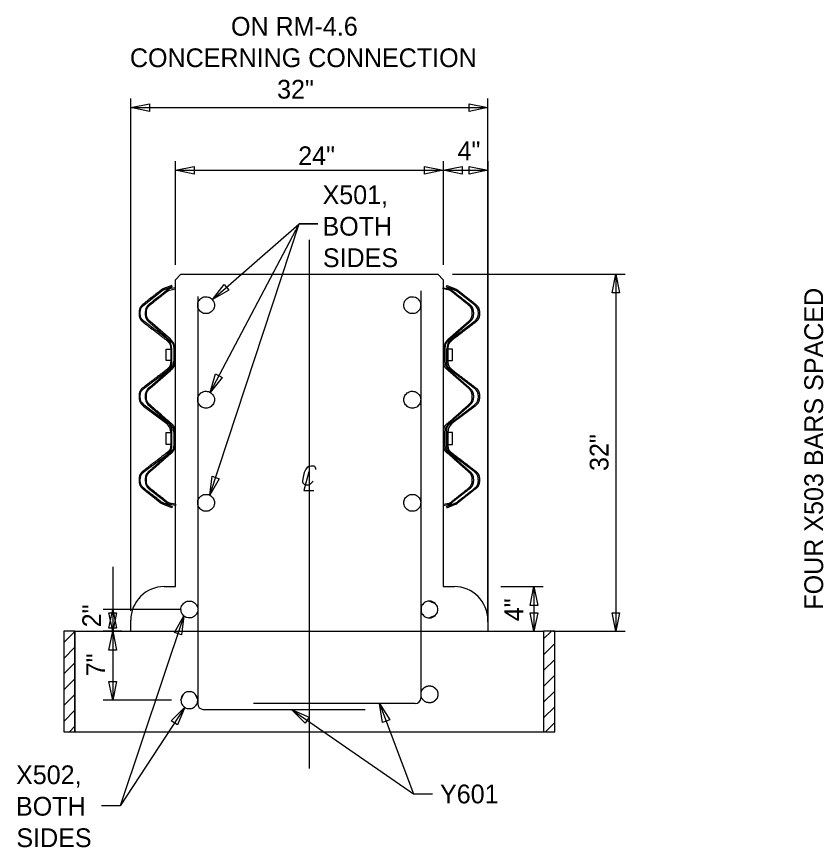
# Model space of a CAD drawing. Extents: x 0 to 680, y 0 to 440.
# Drawn here: x 167 to 287.1, y 191.7 to 315.4 of the extents above; entities that cross this region are included whole.
import ezdxf

# ---------------------------------------------------------------- set-up
doc = ezdxf.new("R2010")
doc.units = 0
doc.layers.add('Default', color=7, linetype='Continuous')

msp = doc.modelspace()

# ---------------------------------------------------------------- linework, layer by layer
at = {"layer": 'Default'}
for p, q in [((183.96, 226.91), (183.96, 303.25)), ((183.96, 301.87), (237.16, 301.87)), ((190.61, 278.45), (190.61, 293.91)), ((230.51, 293.91), (230.51, 278.45)), ((195.76, 244.12), (209.03, 284.55)), ((195.79, 259.44), (209.03, 284.55)), ((196.12, 273.27), (209.03, 284.55)), ((209.03, 284.55), (211.83, 284.55)), ((211.83, 284.55), (209.03, 284.55)), ((210.56, 282.16), (210.56, 203.44)), ((231.89, 277.04), (257.61, 277.04)), ((256.22, 277.04), (256.22, 223.86)), ((190.08, 275.38), (188.75, 274.85)), ((190.61, 275.04), (189.69, 274.85)), ((189.72, 274.68), (190.61, 274.85)), ((190.13, 275.18), (190.08, 275.38)), ((190.61, 274.85), (190.61, 275.04)), ((230.51, 275.04), (231.42, 274.85)), ((230.51, 274.85), (230.51, 275.04)), ((231.39, 274.68), (230.51, 274.85)), ((230.98, 275.18), (231.03, 275.38)), ((231.03, 275.38), (232.36, 274.85)), ((185.95, 272.49), (188.61, 274.57)), ((187.09, 273.38), (187, 273.55)), ((188, 273.38), (187.89, 273.55)), ((188.19, 274.24), (188.08, 274.41)), ((189.08, 274.24), (189, 274.38)), ((193.93, 273.71), (193.93, 213.06)), ((227.18, 274.57), (227.18, 213.92)), ((232.03, 274.24), (232.11, 274.38)), ((235.16, 272.49), (232.5, 274.57)), ((232.95, 274.24), (233.03, 274.41)), ((233.11, 273.38), (233.22, 273.55)), ((234.03, 273.38), (234.11, 273.55)), ((189.41, 267.37), (185.98, 270)), ((189.86, 267.37), (186.86, 270)), ((231.26, 267.37), (234.25, 270)), ((231.7, 267.37), (235.14, 270)), ((187.09, 269.14), (186.98, 268.97)), ((187.95, 269.06), (187.83, 268.89)), ((233.17, 269.06), (233.28, 268.89)), ((234.03, 269.14), (234.14, 268.97)), ((188.19, 268.31), (188.08, 268.14)), ((189, 268.12), (188.92, 267.98)), ((232.11, 268.12), (232.2, 267.98)), ((232.92, 268.31), (233.03, 268.14)), ((190.08, 265.65), (189.91, 265.65)), ((190.08, 264.13), (190.08, 265.95)), ((190.36, 265.95), (190.36, 264.13)), ((190.52, 265.65), (190.36, 265.65)), ((190.52, 264.13), (190.52, 265.95)), ((230.59, 264.13), (230.59, 265.95)), ((230.59, 265.65), (230.76, 265.65)), ((230.76, 265.95), (230.76, 264.13)), ((231.03, 264.13), (231.03, 265.95)), ((231.03, 265.65), (231.2, 265.65)), ((190.08, 264.43), (189.91, 264.43)), ((190.52, 264.43), (190.36, 264.43)), ((230.59, 264.43), (230.76, 264.43)), ((231.03, 264.43), (231.2, 264.43)), ((185.98, 260.08), (189.41, 262.71)), ((189.8, 262.88), (186.78, 260.22)), ((186.86, 260.08), (189.86, 262.71)), ((234.25, 260.08), (231.26, 262.71)), ((231.31, 262.88), (234.33, 260.22)), ((235.14, 260.08), (231.7, 262.71)), ((187.95, 261.02), (187.83, 261.16)), ((188.19, 261.77), (188.08, 261.94)), ((189, 261.94), (188.92, 262.1)), ((232.14, 261.94), (232.2, 262.1)), ((232.92, 261.77), (233.03, 261.94)), ((233.17, 261.02), (233.28, 261.16)), ((187.09, 260.91), (186.98, 261.08)), ((234.03, 260.91), (234.14, 261.08)), ((185.87, 257.42), (189.33, 254.79)), ((189.41, 254.93), (185.98, 257.56)), ((186.78, 257.42), (189.77, 254.79)), ((234.33, 257.42), (231.34, 254.79)), ((231.7, 254.93), (235.14, 257.56)), ((235.25, 257.42), (231.78, 254.79)), ((187.09, 256.73), (186.98, 256.56)), ((187.95, 256.64), (187.83, 256.48)), ((233.17, 256.64), (233.28, 256.48)), ((234.03, 256.73), (234.14, 256.56)), ((188.19, 255.87), (188.08, 255.73)), ((189, 255.7), (188.89, 255.54)), ((232.14, 255.7), (232.23, 255.54)), ((232.92, 255.87), (233.03, 255.73)), ((189.91, 253.54), (189.91, 251.68)), ((190.08, 253.21), (189.91, 253.21)), ((190.08, 251.68), (190.08, 253.54)), ((190.36, 253.54), (190.36, 251.68)), ((190.52, 253.21), (190.36, 253.21)), ((190.52, 251.68), (190.52, 253.54)), ((230.59, 251.68), (230.59, 253.54)), ((230.59, 253.21), (230.76, 253.21)), ((230.76, 253.54), (230.76, 251.68)), ((231.03, 251.68), (231.03, 253.54)), ((231.03, 253.21), (231.2, 253.21)), ((231.2, 253.54), (231.2, 251.68)), ((190.08, 251.99), (189.91, 251.99)), ((190.52, 251.99), (190.36, 251.99)), ((230.59, 251.99), (230.76, 251.99)), ((231.03, 251.99), (231.2, 251.99)), ((185.98, 247.67), (189.41, 250.27)), ((235.14, 247.67), (231.7, 250.27)), ((187.95, 248.58), (187.83, 248.75)), ((188.19, 249.33), (188.08, 249.49)), ((189, 249.52), (188.92, 249.66)), ((232.11, 249.52), (232.2, 249.66)), ((232.92, 249.33), (233.03, 249.49)), ((233.17, 248.58), (233.28, 248.75)), ((187.09, 248.5), (186.98, 248.66)), ((234.03, 248.5), (234.14, 248.66)), ((185.84, 245.01), (188.5, 242.93)), ((186.75, 245.01), (189.41, 242.93)), ((187.09, 244.26), (187, 244.12)), ((188, 244.26), (187.89, 244.12)), ((234.36, 245.01), (231.7, 242.93)), ((235.27, 245.01), (232.61, 242.93)), ((233.11, 244.26), (233.22, 244.12)), ((234.03, 244.26), (234.11, 244.12)), ((188.17, 243.4), (188.08, 243.26)), ((190.08, 242.26), (188.75, 242.79)), ((189.08, 243.4), (189, 243.26)), ((190.61, 242.79), (189.72, 242.96)), ((230.51, 242.79), (231.39, 242.96)), ((231.03, 242.26), (232.36, 242.79)), ((232.03, 243.4), (232.11, 243.26)), ((232.95, 243.4), (233.03, 243.26)), ((190.13, 242.46), (190.08, 242.26)), ((230.98, 242.46), (231.03, 242.26)), ((181.27, 233.45), (181.27, 227.11)), ((188.94, 230.51), (190.61, 230.51)), ((230.51, 230.51), (232.17, 230.51)), ((239.07, 230.51), (245.42, 230.51)), ((244.03, 230.51), (244.03, 223.86)), ((228.46, 228.35), (229.32, 227.99)), ((191.3, 227.11), (179.85, 227.11)), ((181.27, 227.11), (181.27, 223.86)), ((191.88, 226.16), (182.4, 197.87)), ((229.32, 226.22), (228.46, 225.86)), ((175.64, 223.84), (173.99, 222.18)), ((175.64, 223.86), (175.64, 208.9)), ((182.57, 223.86), (179.85, 223.86)), ((181.27, 223.86), (181.27, 213.61)), ((183.96, 223.86), (237.16, 223.86)), ((238.54, 223.86), (245.42, 223.86)), ((245.47, 223.86), (245.47, 208.9)), ((246.6, 223.85), (245.47, 222.73)), ((246.86, 223.86), (257.61, 223.86)), ((247.13, 222.03), (245.47, 220.37)), ((175.64, 221.48), (173.99, 219.82)), ((175.64, 219.15), (173.99, 217.5)), ((247.13, 219.67), (245.47, 218.02)), ((175.64, 216.8), (173.99, 215.14)), ((247.13, 217.32), (245.47, 215.66)), ((175.64, 214.44), (173.99, 212.79)), ((191.44, 213.61), (191.8, 214.47)), ((193.57, 214.47), (193.93, 213.61)), ((247.13, 214.96), (245.47, 213.31)), ((190.05, 213.61), (179.85, 213.61)), ((226.35, 213.08), (202.24, 213.08)), ((221, 213.08), (226.1, 199.67)), ((175.64, 212.09), (173.99, 210.43)), ((191.99, 212.56), (182.4, 197.87)), ((194.76, 212.23), (218.87, 212.23)), ((207.92, 212.23), (226.1, 199.67)), ((247.13, 212.61), (245.47, 210.95)), ((174.81, 208.9), (175.64, 209.73)), ((247.13, 210.25), (245.75, 208.9)), ((175.64, 208.9), (245.47, 208.9)), ((226.1, 199.67), (228.9, 199.67)), ((182.4, 197.87), (179.6, 197.87))]:
    msp.add_line(p, q, dxfattribs=at)
for points in [[(237.16, 293.91), (237.16, 225.25), (237.16, 303.25)], [(190.61, 292.53), (230.51, 292.53), (237.16, 292.53)], [(190.61, 230.51), (190.61, 276.21), (191.44, 277.04), (229.68, 277.04), (230.51, 276.21), (230.51, 230.51)], [(189.91, 264.18), (189.25, 264.18), (189.25, 265.9), (189.91, 265.9)], [(231.2, 264.18), (231.87, 264.18), (231.87, 265.9), (231.2, 265.9)], [(189.91, 251.71), (189.25, 251.71), (189.25, 253.46), (189.91, 253.46)], [(231.2, 251.71), (231.87, 251.71), (231.87, 253.46), (231.2, 253.46)], [(211.55, 247.94), (211.53, 248.16), (211.44, 248.3), (211.36, 248.39), (211.3, 248.44), (211.06, 248.47), (210.81, 248.47), (210.47, 248.39), (210.25, 248.28), (210.03, 248), (209.81, 247.53), (209.7, 247.08), (209.59, 246.56), (209.56, 246.23), (209.56, 246.14), (209.59, 246), (209.64, 245.92), (209.7, 245.86), (209.81, 245.78), (209.92, 245.73), (210.06, 245.7), (210.25, 245.7), (210.45, 245.7), (210.56, 245.73), (210.64, 245.78), (210.75, 245.84), (210.89, 245.98), (211, 246.09), (211.11, 246.23)], [(210.47, 247.61), (209.73, 244.81), (211.22, 244.81)], [(190.61, 242.79), (190.61, 242.62), (189.69, 242.79)], [(230.51, 242.79), (230.51, 242.62), (231.42, 242.79)], [(175.64, 223.86), (183.96, 223.86), (183.96, 225.53)], [(237.16, 225.53), (237.16, 223.86), (245.47, 223.86)]]:
    msp.add_lwpolyline(points, dxfattribs=at)
for points in [[(186.75, 301.31), (183.96, 301.87), (186.75, 302.42)], [(234.36, 302.42), (237.16, 301.87), (234.36, 301.31)], [(193.4, 291.97), (190.61, 292.53), (193.4, 293.08)], [(227.71, 293.08), (230.51, 292.53), (227.71, 291.97)], [(233.31, 291.97), (230.51, 292.53), (233.31, 293.08)], [(234.36, 293.08), (237.16, 292.53), (234.36, 291.97)], [(255.67, 274.27), (256.22, 277.04), (256.78, 274.27)], [(198.59, 274.68), (196.12, 273.27), (197.87, 275.51)], [(197.59, 261.66), (195.79, 259.44), (196.59, 262.19)], [(197.14, 246.59), (195.76, 244.12), (196.09, 246.95)], [(243.48, 227.71), (244.03, 230.51), (244.58, 227.71)], [(180.69, 224.31), (181.27, 227.11), (181.82, 224.31)], [(181.82, 226.63), (181.27, 223.86), (180.69, 226.63)], [(244.58, 226.63), (244.03, 223.86), (243.48, 226.63)], [(256.78, 226.63), (256.22, 223.86), (255.67, 226.63)], [(190.47, 223.67), (191.88, 226.16), (191.52, 223.34)], [(175.64, 208.9), (175.64, 223.86), (173.98, 223.86), (173.98, 208.9)], [(180.69, 221.06), (181.27, 223.86), (181.82, 221.06)], [(247.13, 208.9), (247.13, 223.86), (245.47, 223.86), (245.47, 208.9)], [(181.82, 216.38), (181.27, 213.61), (180.69, 216.38)], [(221.47, 210.26), (221, 213.08), (222.53, 210.67)], [(190, 210.53), (191.99, 212.56), (190.94, 209.93)], [(209.92, 210.17), (207.92, 212.23), (210.56, 211.09)]]:
    msp.add_lwpolyline(points, close=True, dxfattribs=at)
for centre, radius, start, end in [((188.26, 265.96), 1.82, 359.7371, 50.6655), ((188.71, 265.96), 1.82, 359.7371, 50.6655), ((232.41, 265.96), 1.82, 129.3345, 180.2629), ((232.85, 265.96), 1.82, 129.3351, 180.2634), ((188.68, 264.12), 1.68, 310.805, 0.1199), ((232.44, 264.12), 1.68, 179.8801, 229.195), ((188.23, 253.52), 1.68, 359.8802, 49.1952), ((188.68, 253.52), 1.68, 359.8801, 49.1951), ((232.44, 253.52), 1.68, 130.8049, 180.1199), ((232.88, 253.52), 1.68, 130.8048, 180.1198), ((188.94, 225.57), 4.95, 89.989, 135.3148), ((232.17, 225.57), 4.95, 44.6852, 90.011), ((188.95, 225.51), 5, 134.9158, 179.7804), ((232.16, 225.51), 5, 0.2196, 45.0842), ((228.45, 227.14), 1.22, 44.723, 89.7751), ((228.45, 227.07), 1.22, 270.2249, 315.277), ((192.65, 213.61), 1.22, 134.723, 179.7751), ((192.71, 213.61), 1.22, 0.2249, 45.277), ((194.76, 213.06), 0.834, 180.162, 269.8374), ((226.35, 213.92), 0.834, 270.162, 359.8374)]:
    msp.add_arc(centre, radius, start, end, dxfattribs=at)
for points, degree in [([(188.78, 274.85), (188.67, 274.82), (188.58, 274.77), (188.5, 274.71), (187.61, 274.02), (186.73, 273.33), (185.84, 272.63)], 4), ([(189.69, 274.85), (189.58, 274.82), (189.5, 274.79), (189.41, 274.71), (188.53, 274.02), (187.64, 273.33), (186.75, 272.63)], 4), ([(190.13, 275.18), (189.69, 275.02), (189.25, 274.85), (188.8, 274.68), (188.75, 274.66), (188.67, 274.6), (188.61, 274.57)], 4), ([(230.98, 275.18), (231.42, 275.02), (231.87, 274.85), (232.31, 274.68), (232.36, 274.66), (232.45, 274.6), (232.5, 274.57)], 4), ([(231.42, 274.85), (231.53, 274.82), (231.62, 274.79), (231.7, 274.71), (232.59, 274.02), (233.47, 273.33), (234.36, 272.63)], 4), ([(232.34, 274.85), (232.45, 274.82), (232.53, 274.77), (232.61, 274.71), (233.5, 274.02), (234.39, 273.33), (235.27, 272.63)], 4), ([(186.86, 270), (186.5, 270.28), (186.28, 270.75), (186.28, 271.25), (186.28, 271.75), (186.5, 272.22), (186.86, 272.49), (187.74, 273.19), (188.62, 273.88), (189.5, 274.57), (189.58, 274.63), (189.64, 274.66), (189.72, 274.68)], 4), ([(196.06, 273.33), (195.81, 273.55), (195.51, 273.69), (195.18, 273.69), (194.85, 273.69), (194.54, 273.55), (194.29, 273.33), (194.07, 273.08), (193.93, 272.77), (193.93, 272.44), (193.93, 272.11), (194.07, 271.8), (194.29, 271.55), (194.54, 271.33), (194.85, 271.19), (195.18, 271.19), (195.51, 271.19), (195.81, 271.33), (196.06, 271.55), (196.29, 271.8), (196.42, 272.11), (196.42, 272.44), (196.42, 272.77), (196.29, 273.08), (196.06, 273.33)], 3), ([(226.79, 273.33), (226.57, 273.55), (226.24, 273.69), (225.91, 273.69), (225.58, 273.69), (225.27, 273.55), (225.02, 273.33), (224.8, 273.08), (224.66, 272.77), (224.66, 272.44), (224.66, 272.11), (224.8, 271.8), (225.02, 271.55), (225.27, 271.33), (225.58, 271.19), (225.91, 271.19), (226.24, 271.19), (226.57, 271.33), (226.79, 271.55), (227.02, 271.8), (227.15, 272.11), (227.15, 272.44), (227.15, 272.77), (227.02, 273.08), (226.79, 273.33)], 3), ([(234.25, 270), (234.61, 270.28), (234.83, 270.75), (234.83, 271.25), (234.83, 271.75), (234.61, 272.22), (234.25, 272.49), (233.37, 273.19), (232.49, 273.88), (231.62, 274.57), (231.53, 274.63), (231.48, 274.66), (231.39, 274.68)], 4), ([(185.87, 272.63), (185.45, 272.33), (185.2, 271.8), (185.2, 271.25), (185.2, 270.69), (185.44, 270.19), (185.87, 269.83), (187.02, 268.96), (188.18, 268.08), (189.33, 267.2), (189.69, 266.92), (189.91, 266.45), (189.91, 265.95)], 4), ([(185.98, 270), (185.59, 270.28), (185.37, 270.75), (185.37, 271.25), (185.37, 271.75), (185.59, 272.22), (185.95, 272.49)], 3), ([(186.75, 272.63), (186.37, 272.33), (186.12, 271.8), (186.12, 271.25), (186.11, 270.69), (186.35, 270.19), (186.78, 269.83), (187.78, 268.96), (188.78, 268.08), (189.77, 267.2)], 4), ([(235.25, 272.63), (235.66, 272.33), (235.91, 271.8), (235.91, 271.25), (235.91, 270.69), (235.68, 270.19), (235.25, 269.83), (234.09, 268.96), (232.94, 268.08), (231.78, 267.2), (231.42, 266.92), (231.2, 266.45), (231.2, 265.95)], 4), ([(234.36, 272.63), (234.75, 272.33), (235, 271.8), (235, 271.25), (235, 270.69), (234.76, 270.19), (234.33, 269.83), (233.33, 268.96), (232.34, 268.08), (231.34, 267.2)], 4), ([(235.14, 270), (235.52, 270.28), (235.74, 270.75), (235.74, 271.25), (235.74, 271.75), (235.52, 272.22), (235.16, 272.49)], 3), ([(189.77, 267.2), (190.13, 266.92), (190.36, 266.45), (190.36, 265.95)], 2), ([(231.34, 267.2), (230.98, 266.92), (230.76, 266.45), (230.76, 265.95)], 2), ([(189.91, 265.95), (189.91, 265.34), (189.91, 264.74), (189.91, 264.13), (189.91, 263.63), (189.71, 263.18), (189.33, 262.85), (188.18, 261.97), (187.02, 261.1), (185.87, 260.22), (185.45, 259.91), (185.2, 259.39), (185.2, 258.83), (185.2, 258.25), (185.45, 257.72), (185.87, 257.42)], 4), ([(231.2, 265.95), (231.2, 265.34), (231.2, 264.74), (231.2, 264.13), (231.2, 263.63), (231.41, 263.18), (231.78, 262.85), (232.94, 261.97), (234.09, 261.1), (235.25, 260.22), (235.66, 259.91), (235.91, 259.39), (235.91, 258.83), (235.91, 258.25), (235.66, 257.72), (235.25, 257.42)], 4), ([(189.41, 262.71), (189.83, 263.04), (190.08, 263.54), (190.08, 264.13)], 2), ([(189.86, 262.71), (190.27, 263.04), (190.52, 263.54), (190.52, 264.13)], 2), ([(231.26, 262.71), (230.84, 263.04), (230.59, 263.54), (230.59, 264.13)], 2), ([(231.7, 262.71), (231.28, 263.04), (231.03, 263.54), (231.03, 264.13)], 2), ([(185.98, 257.56), (185.59, 257.86), (185.37, 258.31), (185.37, 258.83), (185.37, 259.33), (185.59, 259.8), (185.98, 260.08)], 3), ([(186.78, 260.22), (186.37, 259.91), (186.12, 259.39), (186.12, 258.83), (186.12, 258.25), (186.37, 257.72), (186.78, 257.42)], 3), ([(189.86, 254.93), (188.86, 255.8), (187.86, 256.68), (186.86, 257.56), (186.48, 257.88), (186.28, 258.33), (186.28, 258.83), (186.28, 259.33), (186.5, 259.8), (186.86, 260.08)], 4), ([(231.26, 254.93), (232.25, 255.8), (233.25, 256.68), (234.25, 257.56), (234.63, 257.88), (234.84, 258.33), (234.83, 258.83), (234.83, 259.33), (234.61, 259.8), (234.25, 260.08)], 4), ([(234.33, 260.22), (234.75, 259.91), (235, 259.39), (235, 258.83), (235, 258.25), (234.75, 257.72), (234.33, 257.42)], 3), ([(235.14, 257.56), (235.52, 257.86), (235.74, 258.31), (235.74, 258.83), (235.74, 259.33), (235.52, 259.8), (235.14, 260.08)], 3), ([(196.06, 259.25), (195.81, 259.47), (195.51, 259.61), (195.18, 259.61), (194.85, 259.61), (194.54, 259.47), (194.29, 259.25), (194.07, 259), (193.93, 258.69), (193.93, 258.36), (193.93, 258.03), (194.07, 257.72), (194.29, 257.48), (194.54, 257.25), (194.85, 257.11), (195.18, 257.11), (195.51, 257.11), (195.81, 257.25), (196.06, 257.48), (196.29, 257.72), (196.42, 258.03), (196.42, 258.36), (196.42, 258.69), (196.29, 259), (196.06, 259.25)], 3), ([(226.79, 259.25), (226.57, 259.47), (226.24, 259.61), (225.91, 259.61), (225.58, 259.61), (225.27, 259.47), (225.02, 259.25), (224.8, 259), (224.66, 258.69), (224.66, 258.36), (224.66, 258.03), (224.8, 257.72), (225.02, 257.48), (225.27, 257.25), (225.58, 257.11), (225.91, 257.11), (226.24, 257.11), (226.57, 257.25), (226.79, 257.48), (227.02, 257.72), (227.15, 258.03), (227.15, 258.36), (227.15, 258.69), (227.02, 259), (226.79, 259.25)], 3), ([(190.08, 253.51), (190.08, 254.09), (189.83, 254.62), (189.41, 254.93)], 2), ([(190.52, 253.51), (190.52, 254.09), (190.27, 254.62), (189.86, 254.93)], 2), ([(230.59, 253.51), (230.59, 254.09), (230.84, 254.62), (231.26, 254.93)], 2), ([(231.03, 253.51), (231.03, 254.09), (231.28, 254.62), (231.7, 254.93)], 2), ([(189.91, 251.68), (189.91, 251.19), (189.69, 250.71), (189.33, 250.44)], 2), ([(189.41, 250.3), (189.83, 250.6), (190.08, 251.13), (190.08, 251.68)], 2), ([(190.36, 251.68), (190.36, 251.19), (190.13, 250.71), (189.77, 250.44)], 2), ([(189.86, 250.3), (190.27, 250.6), (190.52, 251.13), (190.52, 251.68)], 2), ([(231.26, 250.3), (230.84, 250.6), (230.59, 251.13), (230.59, 251.68)], 2), ([(230.76, 251.68), (230.76, 251.19), (230.98, 250.71), (231.34, 250.44)], 2), ([(231.7, 250.3), (231.28, 250.6), (231.03, 251.13), (231.03, 251.68)], 2), ([(231.2, 251.68), (231.2, 251.19), (231.42, 250.71), (231.78, 250.44)], 2), ([(189.33, 250.44), (188.18, 249.56), (187.02, 248.68), (185.87, 247.8), (185.44, 247.45), (185.2, 246.95), (185.2, 246.39), (185.2, 245.84), (185.45, 245.31), (185.87, 245.01)], 4), ([(189.77, 250.44), (188.78, 249.56), (187.78, 248.68), (186.78, 247.8), (186.35, 247.45), (186.11, 246.95), (186.12, 246.39), (186.12, 245.84), (186.37, 245.31), (186.75, 245.01)], 4), ([(189.5, 243.07), (188.62, 243.76), (187.74, 244.45), (186.86, 245.14), (186.49, 245.46), (186.28, 245.9), (186.28, 246.39), (186.28, 246.89), (186.5, 247.36), (186.86, 247.64), (187.86, 248.52), (188.86, 249.41), (189.86, 250.3)], 4), ([(231.62, 243.07), (232.49, 243.76), (233.37, 244.45), (234.25, 245.14), (234.62, 245.46), (234.83, 245.9), (234.83, 246.39), (234.83, 246.89), (234.61, 247.36), (234.25, 247.64), (233.25, 248.52), (232.25, 249.41), (231.26, 250.3)], 4), ([(231.34, 250.44), (232.34, 249.56), (233.33, 248.68), (234.33, 247.8), (234.76, 247.45), (235, 246.95), (235, 246.39), (235, 245.84), (234.75, 245.31), (234.36, 245.01)], 4), ([(231.78, 250.44), (232.94, 249.56), (234.09, 248.68), (235.25, 247.8), (235.68, 247.45), (235.91, 246.95), (235.91, 246.39), (235.91, 245.84), (235.66, 245.31), (235.25, 245.01)], 4), ([(188.61, 243.07), (187.72, 243.76), (186.84, 244.45), (185.95, 245.14), (185.57, 245.46), (185.37, 245.9), (185.37, 246.39), (185.37, 246.89), (185.59, 247.36), (185.98, 247.64)], 4), ([(232.5, 243.07), (233.39, 243.76), (234.28, 244.45), (235.16, 245.14), (235.54, 245.46), (235.75, 245.9), (235.74, 246.39), (235.74, 246.89), (235.52, 247.36), (235.14, 247.64)], 4), ([(196.06, 243.9), (195.81, 244.12), (195.51, 244.26), (195.18, 244.26), (194.85, 244.26), (194.54, 244.12), (194.29, 243.9), (194.07, 243.65), (193.93, 243.34), (193.93, 243.01), (193.93, 242.68), (194.07, 242.35), (194.29, 242.12), (194.54, 241.87), (194.85, 241.76), (195.18, 241.76), (195.51, 241.76), (195.81, 241.87), (196.06, 242.12), (196.29, 242.35), (196.42, 242.68), (196.42, 243.01), (196.42, 243.34), (196.29, 243.65), (196.06, 243.9)], 3), ([(226.79, 243.9), (226.57, 244.12), (226.24, 244.26), (225.91, 244.26), (225.58, 244.26), (225.27, 244.12), (225.02, 243.9), (224.8, 243.65), (224.66, 243.34), (224.66, 243.01), (224.66, 242.68), (224.8, 242.35), (225.02, 242.12), (225.27, 241.87), (225.58, 241.76), (225.91, 241.76), (226.24, 241.76), (226.57, 241.87), (226.79, 242.12), (227.02, 242.35), (227.15, 242.68), (227.15, 243.01), (227.15, 243.34), (227.02, 243.65), (226.79, 243.9)], 3), ([(188.78, 242.79), (188.67, 242.82), (188.58, 242.87), (188.5, 242.93)], 2), ([(190.13, 242.46), (189.69, 242.62), (189.25, 242.79), (188.8, 242.96), (188.75, 242.98), (188.67, 243.04), (188.61, 243.07)], 4), ([(189.41, 242.93), (189.5, 242.84), (189.58, 242.82), (189.69, 242.79)], 2), ([(189.72, 242.96), (189.64, 242.98), (189.58, 243.01), (189.5, 243.07)], 2), ([(230.98, 242.46), (231.42, 242.62), (231.87, 242.79), (232.31, 242.96), (232.36, 242.98), (232.45, 243.04), (232.5, 243.07)], 4), ([(231.39, 242.96), (231.48, 242.98), (231.53, 243.01), (231.62, 243.07)], 2), ([(231.7, 242.93), (231.62, 242.84), (231.53, 242.82), (231.42, 242.79)], 2), ([(232.34, 242.79), (232.45, 242.82), (232.53, 242.87), (232.61, 242.93)], 2), ([(191.8, 226.22), (192.05, 226), (192.35, 225.86), (192.68, 225.86), (193.02, 225.86), (193.32, 226), (193.57, 226.22), (193.79, 226.47), (193.93, 226.77), (193.93, 227.11), (193.93, 227.44), (193.79, 227.74), (193.57, 227.99), (193.32, 228.21), (193.02, 228.35), (192.68, 228.35), (192.35, 228.35), (192.05, 228.21), (191.8, 227.99), (191.58, 227.74), (191.44, 227.44), (191.44, 227.11), (191.44, 226.77), (191.58, 226.47), (191.8, 226.22)], 3), ([(228.46, 228.35), (228.12, 228.35), (227.79, 228.21), (227.57, 227.99), (227.32, 227.74), (227.21, 227.44), (227.21, 227.11), (227.21, 226.77), (227.32, 226.47), (227.57, 226.22), (227.79, 226), (228.12, 225.86), (228.46, 225.86)], 3), ([(229.32, 226.22), (229.57, 226.47), (229.7, 226.77), (229.7, 227.11), (229.7, 227.44), (229.57, 227.74), (229.32, 227.99)], 3), ([(227.57, 213.58), (227.79, 213.33), (228.12, 213.22), (228.46, 213.22), (228.79, 213.22), (229.09, 213.33), (229.32, 213.58), (229.57, 213.8), (229.7, 214.14), (229.7, 214.47), (229.7, 214.8), (229.57, 215.11), (229.32, 215.36), (229.09, 215.59), (228.78, 215.72), (228.46, 215.72), (228.12, 215.72), (227.79, 215.58), (227.57, 215.36), (227.32, 215.11), (227.21, 214.8), (227.21, 214.47), (227.21, 214.14), (227.32, 213.8), (227.57, 213.58)], 4), ([(193.57, 214.47), (193.32, 214.72), (193.02, 214.86), (192.68, 214.86), (192.35, 214.86), (192.05, 214.72), (191.8, 214.47)], 3), ([(191.44, 213.61), (191.44, 213.28), (191.58, 212.95), (191.8, 212.72), (192.05, 212.47), (192.35, 212.36), (192.68, 212.36), (193.02, 212.36), (193.32, 212.47), (193.57, 212.72), (193.79, 212.95), (193.93, 213.28), (193.93, 213.61)], 3)]:
    msp.add_open_spline(points, degree=degree, dxfattribs=at)

# ---------------------------------------------------------------- texts
for s, height, p in [('ON RM-4.6', 2.793, (198.89, 312.59)), ('CONCERNING CONNECTION', 2.7931, (183.83, 307.9)), ('32"', 2.793, (205.76, 303.21)), ('24"', 2.793, (208.9, 293.3)), ('4"', 2.793, (232.64, 294.03)), ('X501,', 2.793, (212.53, 287.49)), ('BOTH', 2.793, (212.52, 282.8)), ('SIDES', 2.793, (212.58, 278.11)), ('X502,', 2.793, (166.87, 201.09)), ('Y601', 2.793, (230.03, 198.23)), ('BOTH', 2.793, (166.86, 196.4)), ('SIDES', 2.793, (166.92, 191.71))]:
    msp.add_text(s, height=height, dxfattribs=at).set_placement(p)
for s, height, p in [('FOUR X503 BARS SPACED', 2.7931, (287.1, 227.08)), ('32"', 2.793, (255.13, 247.74)), ('4"', 2.793, (242.42, 225.36)), ('2"', 2.793, (179.54, 224.45)), ('7"', 2.793, (180.13, 217.16))]:
    msp.add_text(s, height=height, rotation=90, dxfattribs=at).set_placement(p)

doc.saveas('drawing.dxf')
